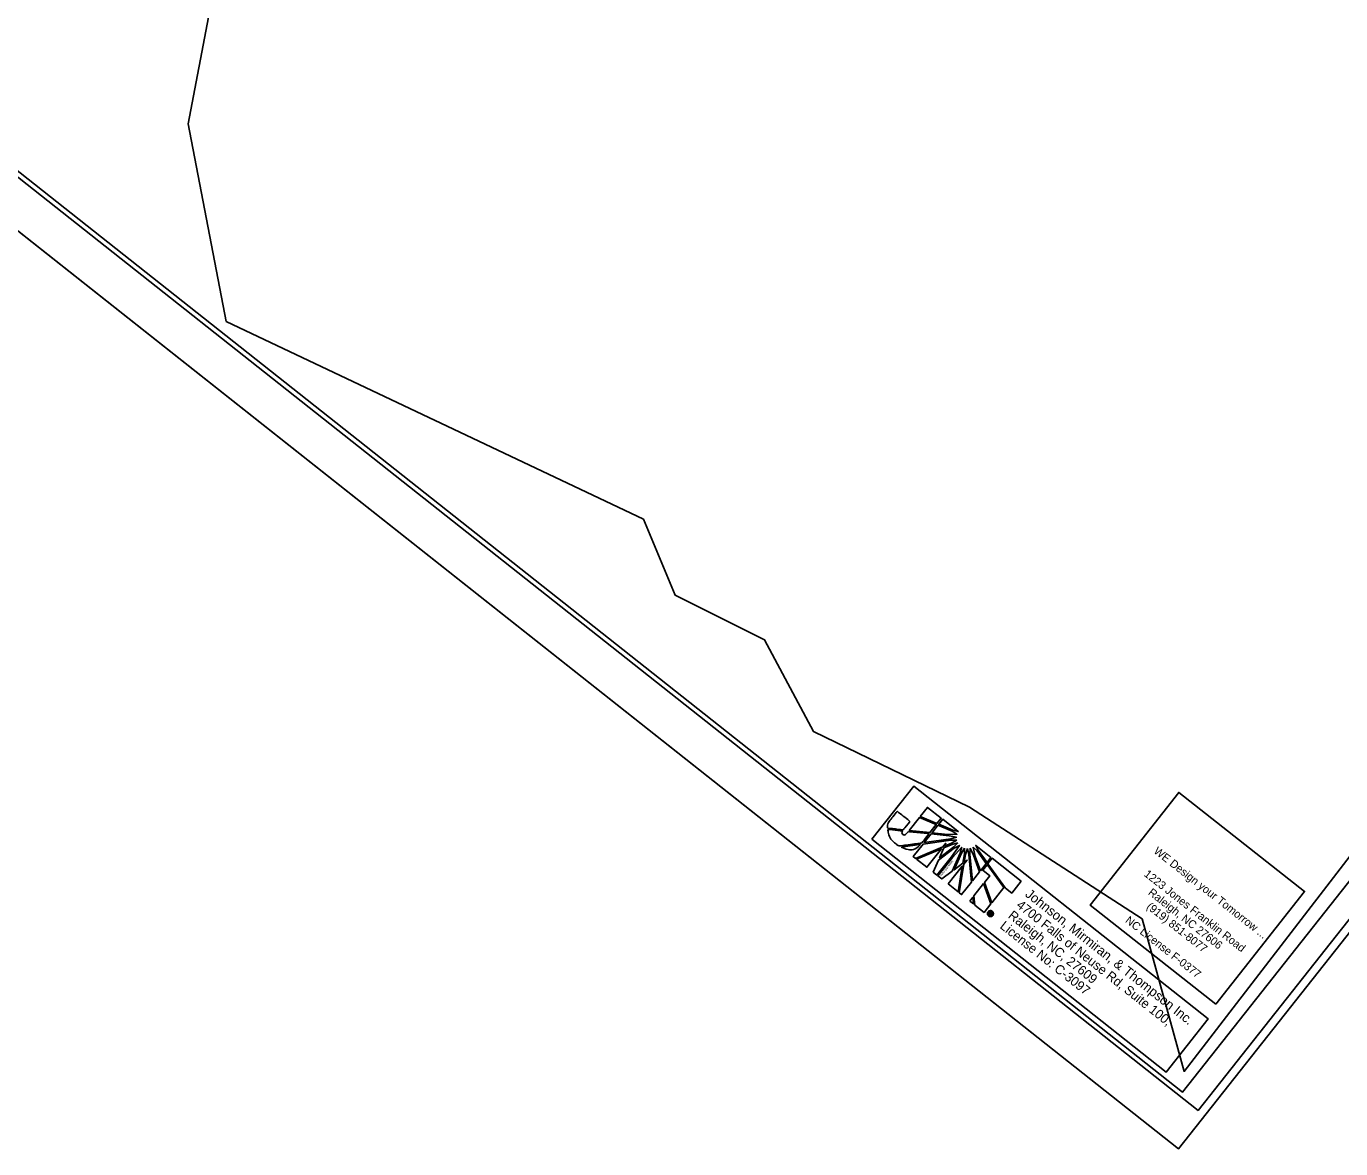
# Model space of a CAD drawing. Extents: x 556999 to 559002, y 505273 to 507273.
# Drawn here: x 557706 to 558407, y 505366 to 505964 of the extents above; entities that cross this region are included whole.
import ezdxf

# ---------------------------------------------------------------- set-up
doc = ezdxf.new("R2010")
doc.units = 0
for name, color, linetype in [('Prop Dimension Text', 7, 'Continuous'), ('Prop DSN Text', 7, 'Continuous'), ('Sheet Border Standard 30in CELL', 7, 'Continuous'), ('Sheet Clip Boundary CELL', 7, 'Continuous'), ('Sheet Cutting Line CELL', 7, 'Continuous'), ('Sheet Plot Border Inside CELL', 7, 'Continuous'), ('Sheet Plot Border Outside CELL', 7, 'Continuous')]:
    doc.layers.add(name, color=color, linetype=linetype)

msp = doc.modelspace()

# ---------------------------------------------------------------- linework, layer by layer
at = {"layer": 'Prop Dimension Text'}
for p, q in [((558186.3, 505547.86), (558182.45, 505542.98)), ((558193.64, 505542.06), (558186.3, 505547.86)), ((558182.01, 505542.43), (558176.6, 505535.57)), ((558190.98, 505538.69), (558182.01, 505542.43)), ((558182.45, 505542.98), (558191.4, 505539.22)), ((558187.62, 505534.43), (558190.98, 505538.69)), ((558191.91, 505538.29), (558188.77, 505534.31)), ((558191.4, 505539.22), (558193.64, 505542.06)), ((558199.41, 505535.13), (558191.91, 505538.29)), ((558194.44, 505541.49), (558192.36, 505538.86)), ((558192.36, 505538.86), (558199.86, 505535.7)), ((558202.71, 505534.97), (558194.44, 505541.49)), ((558176.6, 505535.57), (558187.62, 505534.43)), ((558188.26, 505533.67), (558184.65, 505529.09)), ((558184.65, 505529.09), (558198.76, 505531.04)), ((558197.83, 505532.7), (558188.26, 505533.67)), ((558188.77, 505534.31), (558197.04, 505533.45)), ((558197.04, 505533.45), (558202.04, 505533.52)), ((558201.75, 505531.91), (558197.83, 505532.7)), ((558198.76, 505531.04), (558201.75, 505531.91)), ((558202.04, 505533.52), (558199.41, 505535.13)), ((558199.86, 505535.7), (558202.71, 505534.97)), ((558184.03, 505528.31), (558178.77, 505521.64)), ((558179.98, 505520.68), (558194.55, 505526.8)), ((558193.72, 505525.75), (558180.55, 505520.24)), ((558198.76, 505530.39), (558184.03, 505528.31)), ((558186.03, 505515.91), (558193.72, 505525.75)), ((558200.53, 505526.02), (558192.19, 505519.71)), ((558192.75, 505520.92), (558200.44, 505526.76)), ((558195.05, 505526.27), (558192.75, 505520.92)), ((558194.55, 505526.8), (558196.08, 505528.74)), ((558199.51, 505528.14), (558195.05, 505526.27)), ((558196.08, 505528.74), (558195.39, 505527.12)), ((558195.39, 505527.12), (558199.14, 505528.71)), ((558201.9, 505530.35), (558198.76, 505530.39)), ((558199.13, 505521.53), (558203.39, 505527.58)), ((558199.14, 505528.71), (558201.9, 505530.35)), ((558199.46, 505513.77), (558203.72, 505523.5)), ((558202.44, 505528.86), (558199.51, 505528.14)), ((558204.6, 505526.62), (558199.65, 505521.12)), ((558200.44, 505526.76), (558202.44, 505528.86)), ((558204.42, 505523.48), (558200.47, 505514.55)), ((558203.39, 505527.58), (558200.53, 505526.02)), ((558203.72, 505523.5), (558204.6, 505526.62)), ((558206.04, 505526.02), (558204.42, 505523.48)), ((558205.98, 505523.03), (558206.04, 505526.02)), ((558207.6, 505525.85), (558206.64, 505522.79)), ((558208.36, 505522.81), (558207.6, 505525.85)), ((558209.16, 505526.06), (558208.98, 505522.91)), ((558210.87, 505522.4), (558209.16, 505526.06)), ((558210.7, 505526.69), (558211.79, 505521.74)), ((558212.74, 505524.61), (558210.7, 505526.69)), ((558220.19, 505521.11), (558212.07, 505527.58)), ((558212.07, 505527.58), (558213.36, 505524.98)), ((558217.66, 505517.91), (558212.74, 505524.61)), ((558213.36, 505524.98), (558218.1, 505518.47)), ((558178.77, 505521.64), (558179.98, 505520.68)), ((558180.55, 505520.24), (558186.03, 505515.91)), ((558192.19, 505519.71), (558189.39, 505513.32)), ((558191.4, 505511.74), (558199.13, 505521.53)), ((558199.65, 505521.12), (558191.92, 505511.32)), ((558204.91, 505516.58), (558197.37, 505507.03)), ((558200.47, 505514.55), (558205.17, 505518.09)), ((558202.63, 505502.87), (558204.91, 505516.58)), ((558205.74, 505517.64), (558203.21, 505502.36)), ((558205.17, 505518.09), (558205.98, 505523.03)), ((558207.43, 505519.78), (558205.74, 505517.64)), ((558206.64, 505522.79), (558205.91, 505518.63)), ((558205.91, 505518.63), (558207.43, 505519.78)), ((558209.71, 505507.93), (558208.36, 505522.81)), ((558208.98, 505522.91), (558210.31, 505508.7)), ((558214.02, 505513.4), (558210.87, 505522.4)), ((558211.79, 505521.74), (558214.54, 505514.06)), ((558214.54, 505514.06), (558217.66, 505517.91)), ((558218.1, 505517.29), (558215.76, 505514.33)), ((558218.1, 505518.47), (558220.19, 505521.11)), ((558218.14, 505517.34), (558218.1, 505517.29)), ((558226.96, 505505.1), (558218.14, 505517.34)), ((558218.55, 505517.86), (558218.48, 505517.78)), ((558218.48, 505517.78), (558227.95, 505504.77)), ((558220.79, 505520.7), (558218.55, 505517.86)), ((558236.24, 505508.51), (558220.79, 505520.7)), ((558189.39, 505513.32), (558191.4, 505511.74)), ((558191.92, 505511.32), (558193.96, 505509.72)), ((558193.96, 505509.72), (558199.46, 505513.77)), ((558210.31, 505508.7), (558214.02, 505513.4)), ((558215.76, 505514.33), (558219.53, 505511.36)), ((558219.53, 505511.36), (558216.75, 505507.83)), ((558197.37, 505507.03), (558202.63, 505502.87)), ((558204.5, 505501.34), (558209.71, 505507.93)), ((558216.27, 505507.22), (558211.08, 505500.65)), ((558220.11, 505496.42), (558216.27, 505507.22)), ((558216.75, 505507.83), (558220.56, 505496.99)), ((558220.56, 505496.99), (558226.96, 505505.1)), ((558227.95, 505504.77), (558231.24, 505502.18)), ((558231.24, 505502.18), (558236.24, 505508.51)), ((558203.21, 505502.36), (558204.5, 505501.34)), ((558210.52, 505499.93), (558208.89, 505497.87)), ((558208.89, 505497.87), (558210.8, 505496.37)), ((558210.8, 505496.37), (558210.52, 505499.93)), ((558211.08, 505500.65), (558211.52, 505495.79)), ((558211.52, 505495.79), (558216.51, 505491.86)), ((558216.51, 505491.86), (558220.11, 505496.42)), ((558219.1, 505490.23), (558218.91, 505489.98)), ((558218.91, 505489.98), (558219.1, 505490.23)), ((558218.92, 505489.97), (558218.91, 505489.98)), ((558218.99, 505491.03), (558219.88, 505492.15)), ((558219.25, 505490.83), (558218.99, 505491.03)), ((558219.1, 505490.23), (558219.11, 505490.22)), ((558219.59, 505491.27), (558219.25, 505490.83)), ((558219.8, 505491.1), (558219.59, 505491.27)), ((558219.96, 505491.74), (558219.75, 505491.47)), ((558219.75, 505491.47), (558219.96, 505491.31)), ((558219.96, 505491.31), (558219.8, 505491.1)), ((558219.8, 505491.1), (558219.96, 505491.31)), ((558219.81, 505491.1), (558219.8, 505491.1)), ((558219.88, 505492.15), (558220.34, 505491.79)), ((558220.17, 505491.57), (558219.96, 505491.74)), ((558219.96, 505491.31), (558219.97, 505491.3)), ((558220.34, 505491.79), (558220.17, 505491.57)), ((558220.17, 505491.57), (558220.34, 505491.79)), ((558220.2, 505491.55), (558220.17, 505491.57)), ((558220.34, 505491.79), (558220.41, 505491.73)), ((558220.86, 505492.45), (558220.68, 505492.22)), ((558220.68, 505492.22), (558220.86, 505492.45))]:
    msp.add_line(p, q, dxfattribs=at)
msp.add_lwpolyline([(558156.72, 505530.87), (558313.63, 505406.8), (558336.02, 505435.12), (558179.11, 505559.19)], close=True, dxfattribs=at)
for points in [[(558182.45, 505542.98), (558191.4, 505539.22), (558193.64, 505542.06), (558186.3, 505547.86), (558182.45, 505542.98)], [(558176.6, 505535.57), (558187.62, 505534.43), (558190.98, 505538.69), (558182.01, 505542.43), (558176.6, 505535.57)], [(558191.91, 505538.29), (558188.77, 505534.31), (558197.04, 505533.45), (558202.04, 505533.52), (558199.41, 505535.13), (558191.91, 505538.29)], [(558199.86, 505535.7), (558202.71, 505534.97), (558194.44, 505541.49), (558192.36, 505538.86), (558199.86, 505535.7)], [(558188.26, 505533.67), (558184.65, 505529.09), (558198.76, 505531.04), (558201.75, 505531.91), (558197.83, 505532.7), (558188.26, 505533.67)], [(558201.9, 505530.35), (558198.76, 505530.39), (558184.03, 505528.31), (558178.77, 505521.64), (558179.98, 505520.68), (558194.55, 505526.8), (558196.08, 505528.74), (558195.39, 505527.12), (558199.14, 505528.71), (558201.9, 505530.35)], [(558180.55, 505520.24), (558186.03, 505515.91), (558193.72, 505525.75), (558180.55, 505520.24)], [(558200.53, 505526.02), (558192.19, 505519.71), (558189.39, 505513.32), (558191.4, 505511.74), (558199.13, 505521.53), (558203.39, 505527.58), (558200.53, 505526.02)], [(558204.6, 505526.62), (558199.65, 505521.12), (558191.92, 505511.32), (558193.96, 505509.72), (558199.46, 505513.77), (558203.72, 505523.5), (558204.6, 505526.62)], [(558202.44, 505528.86), (558199.51, 505528.14), (558195.05, 505526.27), (558192.75, 505520.92), (558200.44, 505526.76), (558202.44, 505528.86)], [(558206.04, 505526.02), (558204.42, 505523.48), (558200.47, 505514.55), (558205.17, 505518.09), (558205.98, 505523.03), (558206.04, 505526.02)], [(558207.6, 505525.85), (558206.64, 505522.79), (558205.91, 505518.63), (558207.43, 505519.78), (558205.74, 505517.64), (558203.21, 505502.36), (558204.5, 505501.34), (558209.71, 505507.93), (558208.36, 505522.81), (558207.6, 505525.85)], [(558209.16, 505526.06), (558208.98, 505522.91), (558210.31, 505508.7), (558214.02, 505513.4), (558210.87, 505522.4), (558209.16, 505526.06)], [(558210.7, 505526.69), (558211.79, 505521.74), (558214.54, 505514.06), (558217.66, 505517.91), (558212.74, 505524.61), (558210.7, 505526.69)], [(558213.36, 505524.98), (558218.1, 505518.47), (558220.19, 505521.11), (558212.07, 505527.58), (558213.36, 505524.98)], [(558197.37, 505507.03), (558202.63, 505502.87), (558204.91, 505516.58), (558197.37, 505507.03)], [(558218.14, 505517.34), (558218.1, 505517.29), (558215.76, 505514.33), (558219.53, 505511.36), (558216.75, 505507.83), (558220.56, 505496.99), (558226.96, 505505.1), (558218.14, 505517.34)], [(558236.24, 505508.51), (558220.79, 505520.7), (558218.55, 505517.86), (558218.48, 505517.78), (558227.95, 505504.77), (558231.24, 505502.18), (558236.24, 505508.51)], [(558216.27, 505507.22), (558211.08, 505500.65), (558211.52, 505495.79), (558216.51, 505491.86), (558220.11, 505496.42), (558216.27, 505507.22), (558216.27, 505507.22)], [(558208.89, 505497.87), (558208.89, 505497.87), (558210.8, 505496.37), (558210.52, 505499.93), (558208.89, 505497.87)], [(558220.15, 505490.54), (558220.1, 505490.48), (558220.08, 505490.43), (558220.05, 505490.39), (558219.98, 505490.25), (558219.75, 505490.43)]]:
    msp.add_lwpolyline(points, dxfattribs=at)
for points, degree in [([(558176.98, 505540.39), (558176.98, 505540.39), (558170.18, 505545.76), (558170.18, 505545.76), (558170.18, 505545.76), (558166.82, 505541.5), (558166.82, 505541.5), (558166.82, 505541.5), (558166.46, 505541.06), (558166.46, 505541.06), (558165.41, 505539.72), (558165.01, 505538.32), (558165.09, 505536.82), (558165.09, 505536.82), (558173.36, 505535.81), (558173.43, 505535.89), (558173.43, 505535.89), (558176.98, 505540.39), (558176.98, 505540.39)], 3), ([(558173.2, 505533.44), (558172.77, 505533.78), (558172.58, 505534.32), (558173.06, 505535.26), (558173.06, 505535.26), (558165.21, 505536.16), (558165.21, 505536.16), (558165.49, 505533.16), (558167.28, 505530.1), (558169.48, 505528.37), (558170.05, 505527.92), (558170.52, 505527.62), (558171.22, 505527.26), (558171.22, 505527.26), (558183.24, 505528.88), (558183.24, 505528.88), (558183.24, 505528.88), (558187.15, 505533.83), (558187.15, 505533.83), (558187.15, 505533.83), (558176.11, 505534.96), (558176.11, 505534.96), (558174.65, 505533.1), (558173.81, 505532.96), (558173.2, 505533.44)], 3), ([(558173.2, 505533.44), (558172.77, 505533.78), (558172.58, 505534.32), (558173.06, 505535.26), (558173.06, 505535.26), (558165.21, 505536.16), (558165.21, 505536.16), (558165.49, 505533.16), (558167.28, 505530.1), (558169.48, 505528.37), (558170.05, 505527.92), (558170.52, 505527.62), (558171.22, 505527.26), (558171.22, 505527.26), (558183.24, 505528.88), (558183.24, 505528.88), (558183.24, 505528.88), (558187.15, 505533.83), (558187.15, 505533.83), (558187.15, 505533.83), (558176.11, 505534.96), (558176.11, 505534.96), (558174.65, 505533.1), (558173.81, 505532.96), (558173.2, 505533.44)], 3), ([(558182.63, 505528.1), (558182.63, 505528.1), (558172.25, 505526.71), (558172.25, 505526.71), (558175.59, 505525.19), (558179.84, 505524.85), (558182.63, 505528.1)], 3), ([(558218.91, 505489.98), (558218.57, 505490.25), (558218.37, 505490.6), (558218.32, 505491.04), (558218.26, 505491.47), (558218.37, 505491.86), (558218.65, 505492.21), (558218.92, 505492.56), (558219.28, 505492.76), (558219.7, 505492.79), (558220.13, 505492.83), (558220.51, 505492.73), (558220.86, 505492.45)], 3), ([(558220.68, 505492.22), (558220.4, 505492.44), (558220.09, 505492.53), (558219.75, 505492.5), (558219.41, 505492.46), (558219.11, 505492.29), (558218.89, 505492.02), (558218.68, 505491.74), (558218.58, 505491.42), (558218.63, 505491.07), (558218.67, 505490.72), (558218.83, 505490.44), (558219.1, 505490.23)], 3), ([(558221.15, 505490.24), (558220.88, 505489.89), (558220.52, 505489.69), (558220.09, 505489.63), (558219.66, 505489.59), (558219.27, 505489.7), (558218.92, 505489.97)], 3), ([(558219.11, 505490.22), (558219.39, 505490), (558219.7, 505489.91), (558220.04, 505489.95), (558220.39, 505489.99), (558220.69, 505490.15), (558220.9, 505490.43), (558221.12, 505490.7), (558221.21, 505491.03), (558221.17, 505491.38), (558221.12, 505491.71), (558220.96, 505491.99), (558220.68, 505492.22)], 3), ([(558219.75, 505490.43), (558219.76, 505490.52), (558219.79, 505490.59), (558219.86, 505490.68), (558219.94, 505490.78), (558219.98, 505490.85), (558219.97, 505490.9)], 3), ([(558219.97, 505490.9), (558219.95, 505490.95), (558219.91, 505491.02), (558219.81, 505491.1)], 2), ([(558219.97, 505491.3), (558220.13, 505491.17), (558220.25, 505491.16), (558220.33, 505491.25), (558220.39, 505491.33), (558220.35, 505491.43), (558220.2, 505491.55)], 3), ([(558220.25, 505490.92), (558220.28, 505490.82), (558220.25, 505490.7), (558220.15, 505490.54)], 2), ([(558220.41, 505491.73), (558220.69, 505491.51), (558220.75, 505491.28), (558220.57, 505491.06), (558220.49, 505490.95), (558220.39, 505490.91), (558220.25, 505490.92)], 3), ([(558220.86, 505492.45), (558221.21, 505492.18), (558221.41, 505491.82), (558221.47, 505491.39), (558221.54, 505490.98), (558221.42, 505490.58), (558221.15, 505490.24)], 3)]:
    msp.add_open_spline(points, degree=degree, dxfattribs=at)
at = {"layer": 'Prop DSN Text'}
msp.add_lwpolyline([(558340.1, 505443.02), (558273.02, 505495.76), (558320.24, 505555.82), (558387.32, 505503.07)], close=True, dxfattribs=at)
at = {"layer": 'Sheet Border Standard 30in CELL'}
msp.add_lwpolyline([(558973.57, 506219.71), (557796.95, 507150.06), (557145.7, 506326.43), (558322.33, 505396.07)], close=True, dxfattribs=at)
at = {"layer": 'Sheet Clip Boundary CELL'}
msp.add_lwpolyline([(558069.07, 506542.35), (558502.21, 506199.86), (558564.29, 506127.01), (558761.1, 505975.77), (558323.19, 505407.07), (558300.81, 505488.36), (558208.66, 505547.92), (558125.54, 505588.21), (558099.51, 505637.12), (558051.88, 505660.91), (558034.88, 505701.52), (557812.51, 505806.82), (557792.13, 505912.23), (557814.64, 506029.85), (557725.94, 506096.17), (557744.19, 506089.08), (557749.43, 506157.45), (557759.11, 506179.01), (557817.46, 506256.09), (557969.3, 506353.49), (557953.99, 506367.89), (557981.23, 506420.97), (558000.13, 506451.2)], close=True, dxfattribs=at)
at = {"layer": 'Sheet Cutting Line CELL'}
msp.add_line((556999.2, 506410.4), (558320.16, 505365.92), dxfattribs=at)
at = {"layer": 'Sheet Plot Border Inside CELL'}
msp.add_lwpolyline([(558984.96, 506213.96), (557677.73, 507247.58), (557023.32, 506419.94), (558330.55, 505386.32)], close=True, dxfattribs=at)
at = {"layer": 'Sheet Plot Border Outside CELL'}
msp.add_lwpolyline([(559002.42, 506228.78), (557681.46, 507273.25), (556999.2, 506410.4), (558320.16, 505365.92)], close=True, dxfattribs=at)

# ---------------------------------------------------------------- texts
at = {"layer": 'Prop Dimension Text'}
for s, height, rotation, p in [('www.jmt.com', 1.2413, 231.66667, (558199.36, 505519.73)), ('Johnson, Mirmiran, & Thompson Inc.', 5.1112, 321.66667, (558238, 505500.84)), ('4700 Falls of Neuse Rd, Suite 100, ', 4.9652, 321.66667, (558233.34, 505494.96)), ('Raleigh, NC, 27609', 4.9652, 321.66667, (558228.94, 505489.39)), ('License No: C-3097', 4.9652, 321.66667, (558224.54, 505483.82))]:
    msp.add_text(s, height=height, rotation=rotation, dxfattribs=at).set_placement(p)
at = {"layer": 'Prop DSN Text'}
for s, p in [('WE Design your Tomorrow ...', (558306.57, 505523.82)), ('1223 Jones Franklin Road', (558301.4, 505511.6)), ('Raleigh, NC 27606', (558303.6, 505501.73)), ('(919) 851-8077', (558302.73, 505494.27)), ('NC License F-0377', (558291.41, 505486.89))]:
    msp.add_text(s, height=4.2667, rotation=321.82166, dxfattribs=at).set_placement(p)

doc.saveas('drawing.dxf')
